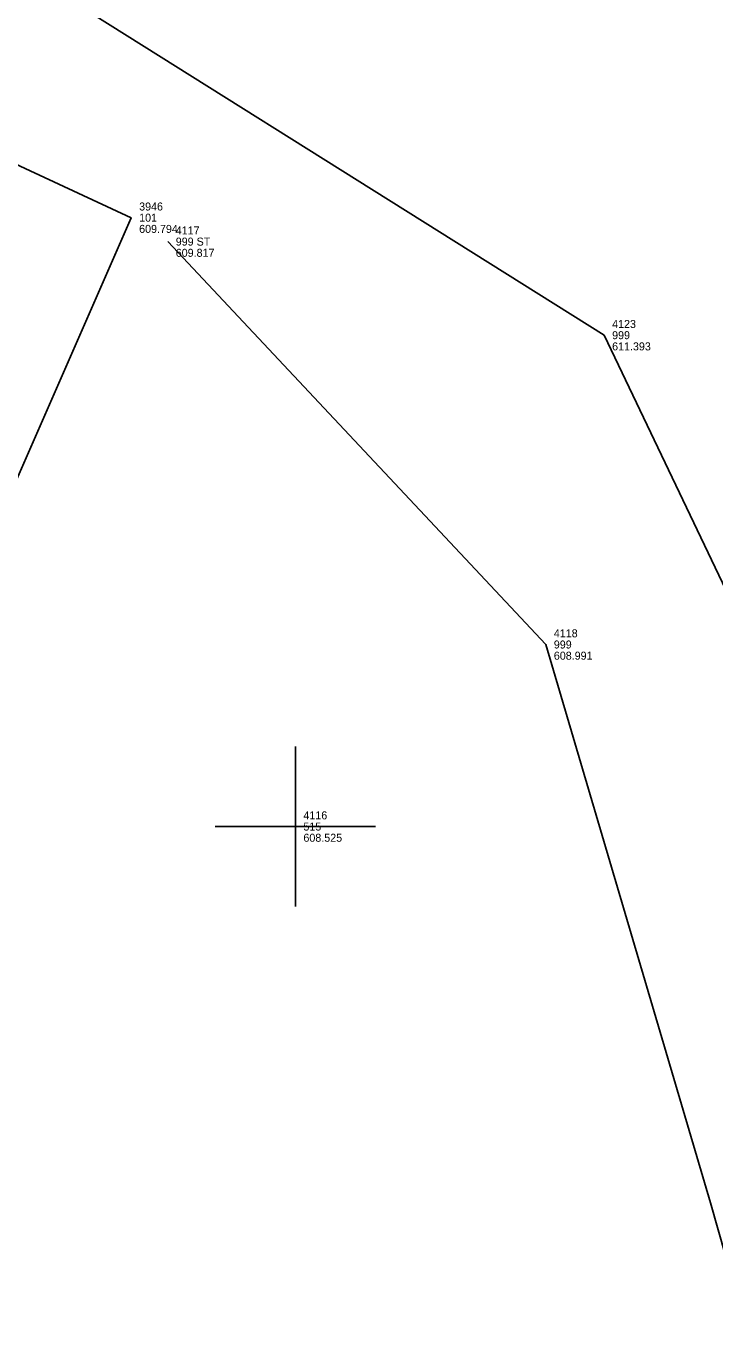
# Model space of a CAD drawing. Extents: x 5447 to 709667, y 4528 to 375505.
# Drawn here: x 709051.07 to 709072.57, y 373735.28 to 373776.23 of the extents above; entities that cross this region are included whole.
import ezdxf

# ---------------------------------------------------------------- set-up
doc = ezdxf.new("R2010")
doc.units = 0
for name, color, linetype in [('SV_BKLN_BKLN', 7, 'Continuous'), ('SV_NODES_ACTIVE_POINT', 7, 'Continuous'), ('SV_NODES_DESCRIPTION', 7, 'Continuous'), ('SV_NODES_ELEVATION', 7, 'Continuous'), ('SV_NODES_PT_NUMBER', 7, 'Continuous'), ('SV_ROAD_BITRD', 7, 'Continuous'), ('SV_SURF_SPOT', 7, 'Continuous')]:
    doc.layers.add(name, color=color, linetype=linetype)

msp = doc.modelspace()

# ---------------------------------------------------------------- linework, layer by layer
at = {"layer": 'SV_BKLN_BKLN'}
for points in [[(709079.463, 373735.459), (709074.818, 373754.637), (709069.114, 373766.576), (709048.004, 373779.831), (709040.694, 373788.163), (709047.474, 373798.35), (709057.157, 373796.406)], [(709055.489, 373769.5), (709067.294, 373756.913), (709072.44, 373739.467), (709075.866, 373727.365)]]:
    msp.add_lwpolyline(points, dxfattribs=at)
at = {"layer": 'SV_NODES_ACTIVE_POINT'}
for p, q in [((709054.346, 373770.247), (709054.346, 373770.247)), ((709055.489, 373769.5), (709055.489, 373769.5)), ((709069.114, 373766.576), (709069.114, 373766.576)), ((709067.294, 373756.913), (709067.294, 373756.913)), ((709072.44, 373739.467), (709072.44, 373739.467))]:
    msp.add_line(p, q, dxfattribs=at)
at = {"layer": 'SV_ROAD_BITRD'}
msp.add_lwpolyline([(709043.626, 373745.753), (709054.346, 373770.247), (709042.144, 373775.917)], dxfattribs=at)
at = {"layer": 'SV_SURF_SPOT'}
for p, q in [((709059.475, 373748.724), (709059.475, 373753.726)), ((709056.974, 373751.225), (709061.976, 373751.225)), ((709059.475, 373751.225), (709059.475, 373751.225))]:
    msp.add_line(p, q, dxfattribs=at)

# ---------------------------------------------------------------- texts
at = {"layer": 'SV_NODES_DESCRIPTION'}
for s, p in [('101', (709054.596, 373770.122)), ('999 ST', (709055.739, 373769.375)), ('999', (709069.364, 373766.451)), ('999', (709067.544, 373756.788)), ('515', (709059.725, 373751.1))]:
    msp.add_text(s, height=0.25, dxfattribs=at).set_placement(p)
at = {"layer": 'SV_NODES_ELEVATION'}
for s, p in [('609.794', (709054.596, 373769.772)), ('609.817', (709055.739, 373769.025)), ('611.393', (709069.364, 373766.101)), ('608.991', (709067.544, 373756.438)), ('608.525', (709059.725, 373750.75))]:
    msp.add_text(s, height=0.25, dxfattribs=at).set_placement(p)
at = {"layer": 'SV_NODES_PT_NUMBER'}
for s, p in [('3946', (709054.596, 373770.472)), ('4117', (709055.739, 373769.725)), ('4123', (709069.364, 373766.801)), ('4118', (709067.544, 373757.138)), ('4116', (709059.725, 373751.45))]:
    msp.add_text(s, height=0.25, dxfattribs=at).set_placement(p)

doc.saveas('drawing.dxf')
